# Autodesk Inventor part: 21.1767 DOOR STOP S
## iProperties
Created: 2007-03
Part Number: 21.1767 DOOR STOP S
Material: Steel
Document SubType Name: Modeling
Designer: Andy Moles
Density: 7.85 g/cm^3
Mass: 115.887 g
Surface Area: 63.6154 cm^2
Volume: 14.7627 cm^3
Author: Andy Moles
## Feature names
1. Base1
2. Chamfer1
3. Chamfer2
4. Chamfer3
5. Chamfer4
